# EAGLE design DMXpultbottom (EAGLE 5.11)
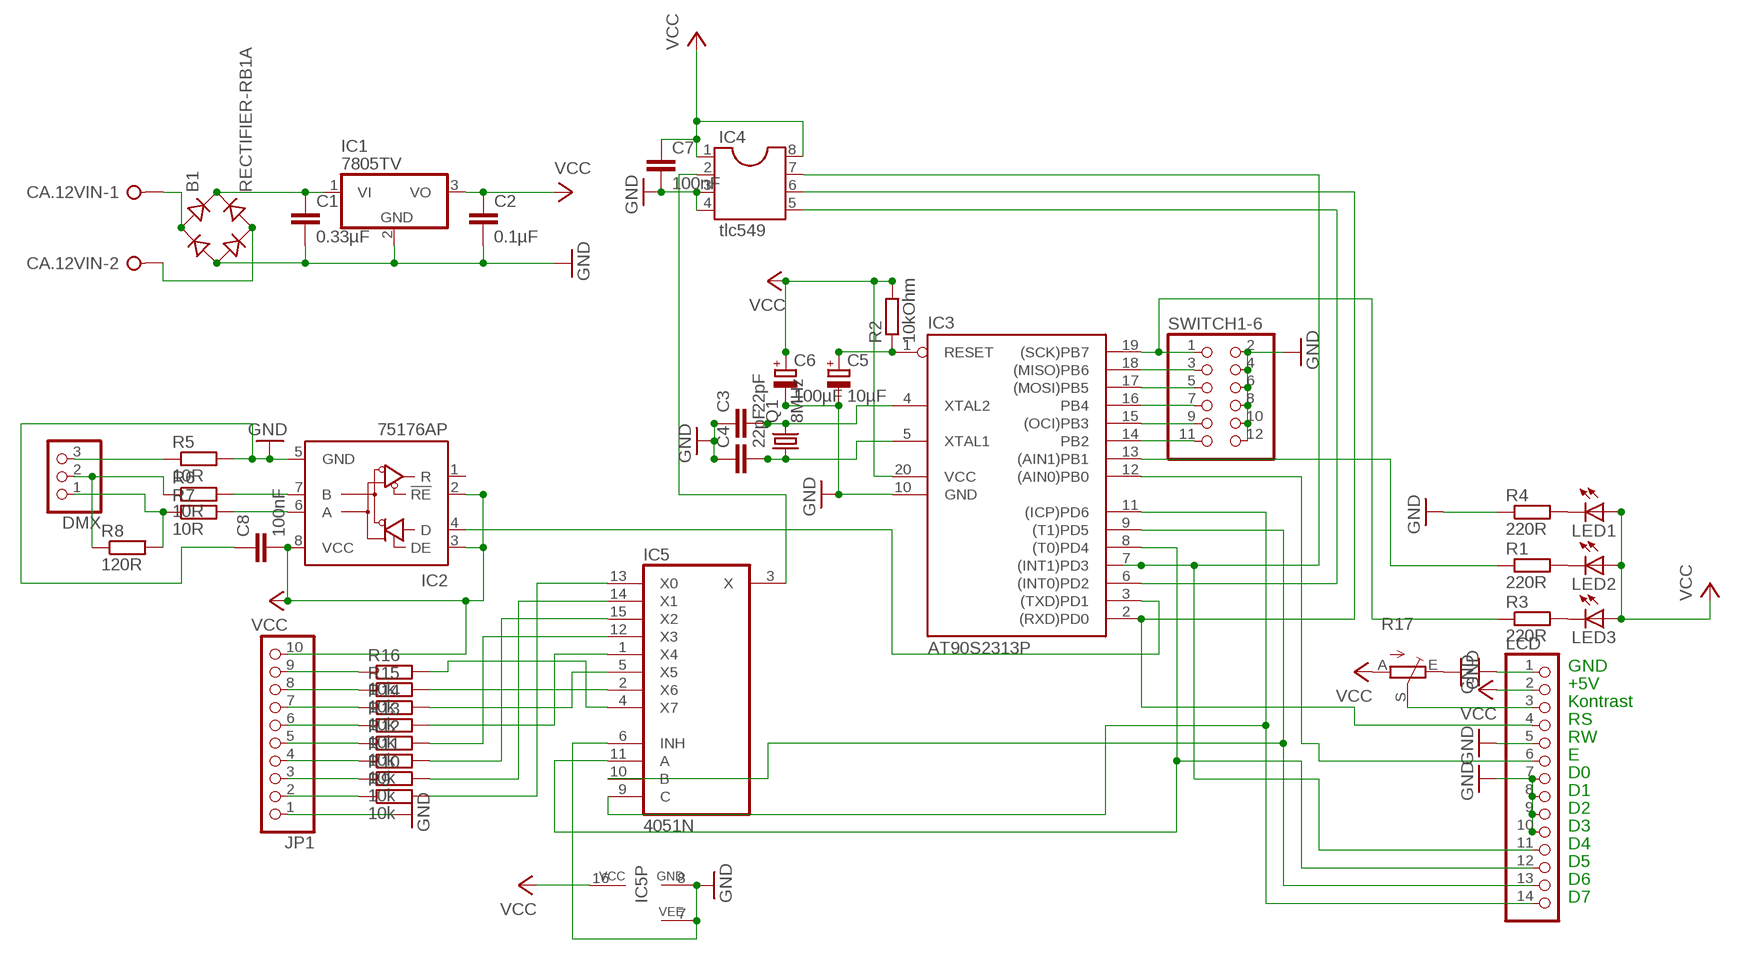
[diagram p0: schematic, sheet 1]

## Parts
B1  RECTIFIER-RB1A  [RB1A]
C1  0.33µF  C-EU025-025X050  [C025-025X050]
C2  0.1µF  C-EU025-025X050  [C025-025X050]
C3  22pF  C-EU025-024X044  [C025-024X044]
C4  22pF  C-EU025-024X044  [C025-024X044]
C5  10µF  CPOL-EUE2,5-6E  [E2,5-6E]
C6  100µF  CPOL-EUE2,5-6E  [E2,5-6E]
C7  100nF  C-EU075-042X103  [C075-042X103]
C8  100nF  C-EU075-032X103  [C075-032X103]
CA.12VIN  W237-02P  [W237-132]
DMX  PINHD-1X3  [1X03]
IC1  7805TV  [TO220V]
IC2  75176AP  [DIL08]
IC3  AT90S2313P  [DIL20]
IC4  tlc549  DIL8  [DIL08]
IC5  4051N  [DIL16]
JP1  PINHD-1X10  [1X10]
LCD  PINHD-1X14  [1X14]
LED1  LED3MM  [LED3MM]
LED2  LED3MM  [LED3MM]
LED3  LED3MM  [LED3MM]
Q1  8MHz  CRYSTALHC49U70  [HC49U70]
R1  220R  R-EU_0207/2V  [0207/2V]
R2  10kOhm  R-EU_0207/2V  [0207/2V]
R3  220R  R-EU_0207/2V  [0207/2V]
R4  220R  R-EU_0207/2V  [0207/2V]
R5  10R  R-EU_0207/2V  [0207/2V]
R6  10R  R-EU_0207/2V  [0207/2V]
R7  10R  R-EU_0207/2V  [0207/2V]
R8  120R  R-EU_0207/2V  [0207/2V]
R9  10k  R-EU_0207/2V  [0207/2V]
R10  10k  R-EU_0207/2V  [0207/2V]
R11  10k  R-EU_0207/2V  [0207/2V]
R12  10k  R-EU_0207/2V  [0207/2V]
R13  10k  R-EU_0207/2V  [0207/2V]
R14  10k  R-EU_0207/2V  [0207/2V]
R15  10k  R-EU_0207/2V  [0207/2V]
R16  10k  R-EU_0207/2V  [0207/2V]
R17  TRIM_EU-B64Y  [B64Y]
SWITCH1-6  PINHD-2X6  [2X06]

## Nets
GND: B1.- C1.2 C2.2 C3.1 C4.1 C5.- C6.- C7.2 C8.1 IC1.2(GND) IC2.5(GND) IC3.10(GND) IC4.3 IC4.4 IC5.6(INH) IC5.7(VEE) IC5.8(GND) JP1.1 LCD.1 LCD.5 LCD.7 LCD.8 LCD.9 LCD.10 R4.1 R5.2 R17.E SWITCH1-6.2 SWITCH1-6.4 SWITCH1-6.6 SWITCH1-6.8 SWITCH1-6.10 SWITCH1-6.12
N$1: IC3.8((T0)PD4) IC5.11(A) LCD.12
N$2: B1.+ C1.1 IC1.1(VI)
N$4: IC3.9((T1)PD5) IC5.10(B) LCD.13
N$5: C5.+ IC3.1(RESET) R2.1
N$6: IC3.2((RXD)PD0) IC4.6 LCD.4
N$7: IC2.4(D) IC3.3((TXD)PD1)
N$8: IC3.6((INT0)PD2) IC4.5
N$9: IC3.7((INT1)PD3) IC4.7 LCD.11
N$10: IC3.11((ICP)PD6) IC5.9(C) LCD.14
N$11: LED2.K(C) R1.2
N$12: IC3.12((AIN0)PB0) LCD.6
N$13: IC3.18((MISO)PB6) SWITCH1-6.3
N$14: IC3.17((MOSI)PB5) SWITCH1-6.5
N$15: IC3.16(PB4) SWITCH1-6.7
N$16: IC3.15((OCI)PB3) SWITCH1-6.9
N$17: IC3.19((SCK)PB7) R3.1 SWITCH1-6.1
N$18: C4.2 IC3.5(XTAL1) Q1.1
N$19: IC3.13((AIN1)PB1) R1.1
N$20: LED3.K(C) R3.2
N$21: LED1.K(C) R4.2
N$22: JP1.9 R16.1
N$23: JP1.8 R15.1
N$24: JP1.7 R14.1
N$25: IC4.2 IC5.3(X)
N$26: JP1.6 R13.1
N$27: IC2.7(B) R6.2
N$28: IC2.6(A) R7.2
N$29: DMX.3 R5.1
N$30: DMX.2 R6.1 R8.1
N$31: DMX.1 R7.1 R8.2
N$32: JP1.5 R12.1
N$33: JP1.3 R10.1
N$34: IC5.13(X0) R9.2
N$35: IC5.14(X1) R10.2
N$36: IC5.15(X2) R11.2
N$37: IC5.12(X3) R12.2
N$38: IC5.1(X4) R13.2
N$39: IC5.5(X5) R14.2
N$40: IC5.2(X6) R15.2
N$41: IC5.4(X7) R16.2
N$42: JP1.2 R9.1
N$43: JP1.4 R11.1
N$44: C3.2 IC3.4(XTAL2) Q1.2
N$45: B1.AC2 CA.12VIN.2
N$46: B1.AC1 CA.12VIN.1
N$47: LCD.3 R17.S
N$48: IC3.14(PB2) SWITCH1-6.11
VCC: C2.1 C6.+ C7.1 C8.2 IC1.3(VO) IC2.2(!RE) IC2.3(DE) IC2.8(VCC) IC3.20(VCC) IC4.1 IC4.8 IC5.16(VCC) JP1.10 LCD.2 LED1.A LED2.A LED3.A R2.2 R17.A
Unconnected: IC2.1(R)

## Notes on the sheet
- GND
- +5V
- Kontrast
- RS
- RW
- E
- D0
- D1
- D2
- D3
- D4
- D5
- D6
- D7

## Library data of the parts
B1 = rectifier:RECTIFIER-: Rectifier
C1-C4 C7 C8 = resistor:C-EU: CAPACITOR, European symbol
C5 C6 = resistor:CPOL-EU: POLARIZED CAPACITOR, European symbol
CA.12VIN = con-wago-508:W237-02P: WAGO SREW CLAMP; OC_FARNELL: unknown; OC_NEWARK: unknown
DMX = pinhead:PINHD-1X3: PIN HEADER
IC1 = linear:78*: Positive VOLTAGE REGULATOR Source: http://cache.national.com/ds/LM/LM78L05.pdf http://www.fairchildsemi.com/ds/LM/LM7805.pdf
IC2 = 751xx:75176A: DIFFERENTIAL BUS TRANSCEIVER Source: http://focus.ti.com/lit/ds/symlink/sn75176a.pdf
IC3 = atmel:AT90S2313: MICROCONTROLLER 2 Kbytes FLASH 128 bytes SRAM 128 bytes EEPROM UART; OC_FARNELL: unknown; OC_NEWARK: unknown
IC4 = ic-package:DIL8: Dual In Line / Socket
IC5 = 40xx:4051: 8-channel ANALOG MULTIPLEXER
JP1 = pinhead:PINHD-1X10: PIN HEADER
LCD = pinhead:PINHD-1X14: PIN HEADER
LED1-LED3 = led:LED: LED
Q1 = crystal:CRYSTAL: CRYSTAL; OC_FARNELL: unknown; OC_NEWARK: unknown
R1-R16 = resistor:R-EU_: RESISTOR, European symbol
R17 = pot:TRIM_EU-: POTENTIOMETER
SWITCH1-6 = pinhead:PINHD-2X6: PIN HEADER

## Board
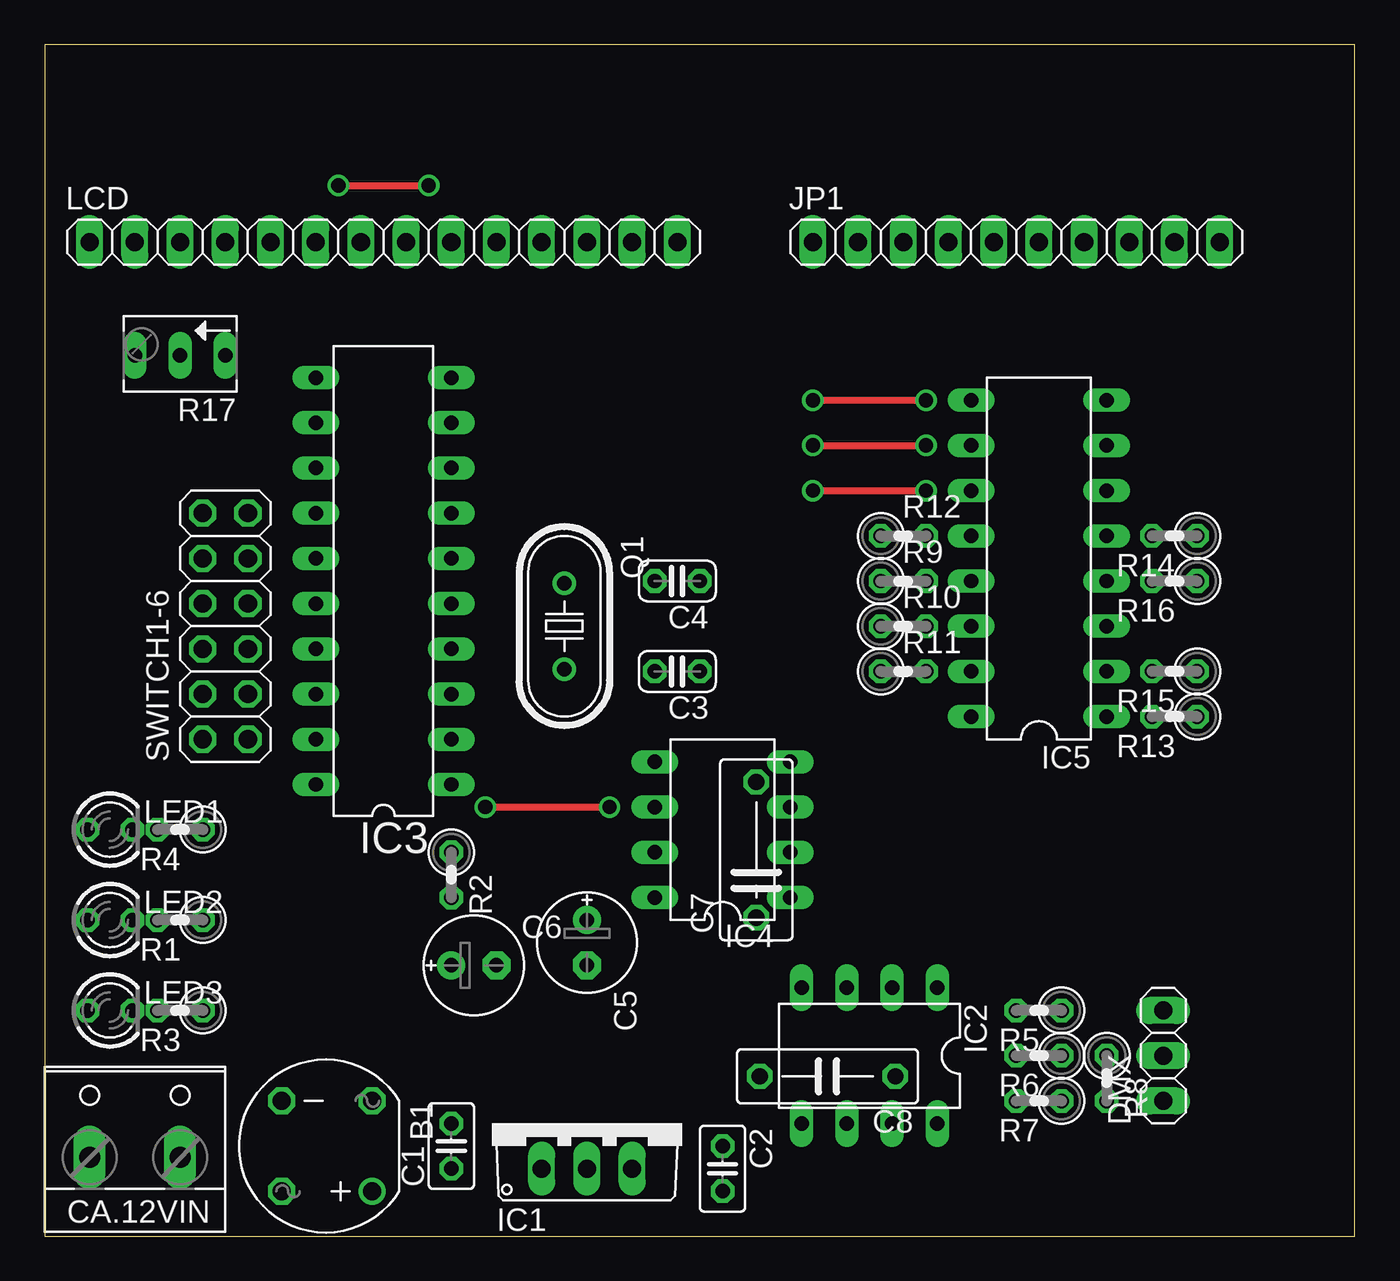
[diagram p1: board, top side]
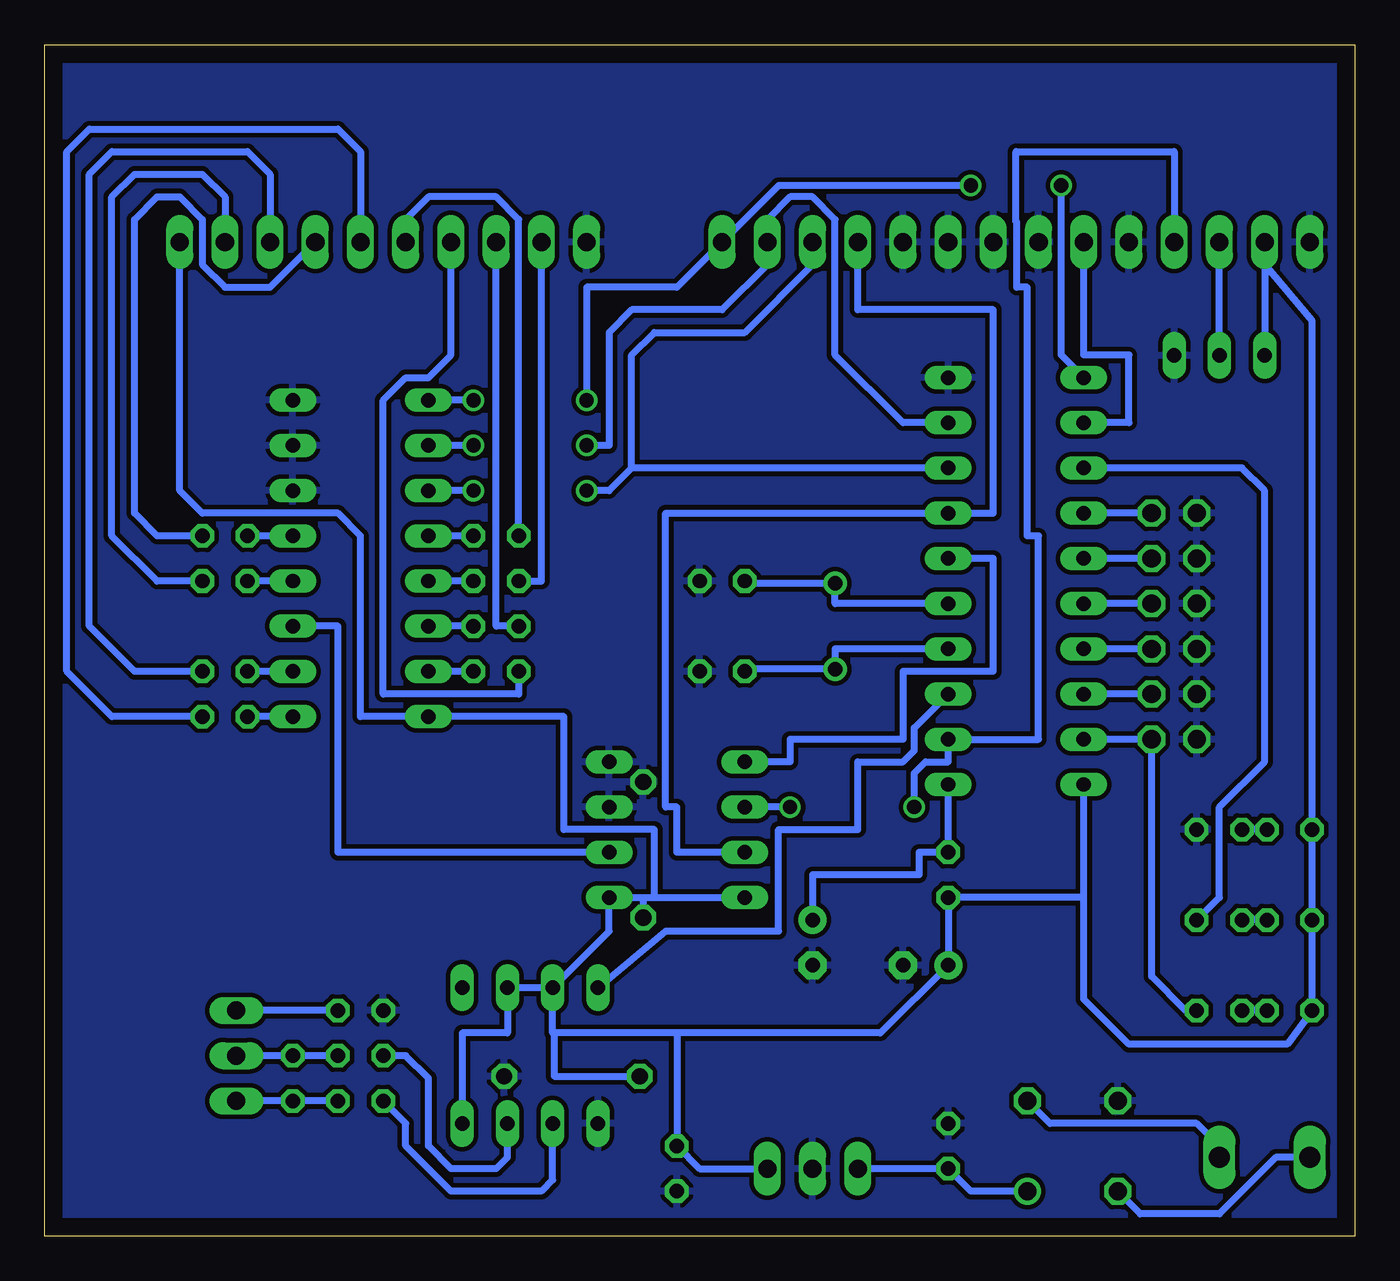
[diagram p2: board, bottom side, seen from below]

Size 73.64 x 66.98 mm. Coordinates in mm from the lower left corner, seen from the top.
Outline: 0,0 73.64,0 73.64,66.98 0,66.98 0,0
Copper layers (1*16): Top 0.035mm / dielectric 1.5mm / Bottom 0.035mm
Design rules "default": minimum track width 10mil, minimum drill 24mil, track to track 8mil, track to pad 8mil, pad to pad 8mil, via to via 8mil, smd to smd 8mil, copper to edge 40mil, drill to drill 8mil, minimum pad ring 10mil, minimum via ring 8mil, stop-mask expansion 4mil, vias tented up to drill 0mil, thermal gap 10mil

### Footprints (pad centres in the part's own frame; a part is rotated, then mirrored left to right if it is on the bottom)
RB1A = drill 1.016 round: + -2.54,2.54 | drill 1.016 octagon: - 2.54,-2.54; AC1 2.54,2.54; AC2 -2.54,-2.54
C025-025X050 = drill 0.813 octagon: 1 -1.27,0; 2 1.27,0
C025-024X044 = drill 0.813 octagon: 1 -1.27,0; 2 1.27,0
E2,5-6E = drill 0.813 pad 1.575 round: + -1.27,0 | drill 0.813 pad 1.575 octagon: - 1.27,0
C075-042X103 = drill 0.914 octagon: 1 -3.81,0; 2 3.81,0
C075-032X103 = drill 0.914 octagon: 1 -3.81,0; 2 3.81,0
W237-132 = drill 1.194 long: 1 -2.54,-0.635; 2 2.54,-0.635
1X03 = drill 1.016 long: 1 -2.54,0; 2 0,0; 3 2.54,0
TO220V = drill 1.016 long: 1 -2.54,-2.54; 2 0,-2.54; 3 2.54,-2.54
DIL08 = drill 0.813 long: 1 -3.81,-3.81; 2 -1.27,-3.81; 3 1.27,-3.81; 4 3.81,-3.81; 5 3.81,3.81; 6 1.27,3.81; 7 -1.27,3.81; 8 -3.81,3.81
DIL20 = drill 0.813 long: 1 -11.43,-3.81; 2 -8.89,-3.81; 3 -6.35,-3.81; 4 -3.81,-3.81; 5 -1.27,-3.81; 6 1.27,-3.81; 7 3.81,-3.81; 8 6.35,-3.81; 9 8.89,-3.81; 10 11.43,-3.81; 11 11.43,3.81; 12 8.89,3.81; 13 6.35,3.81; 14 3.81,3.81; 15 1.27,3.81; 16 -1.27,3.81; 17 -3.81,3.81; 18 -6.35,3.81; 19 -8.89,3.81; 20 -11.43,3.81
DIL16 = drill 0.813 long: 1 -8.89,-3.81; 2 -6.35,-3.81; 3 -3.81,-3.81; 4 -1.27,-3.81; 5 1.27,-3.81; 6 3.81,-3.81; 7 6.35,-3.81; 8 8.89,-3.81; 9 8.89,3.81; 10 6.35,3.81; 11 3.81,3.81; 12 1.27,3.81; 13 -1.27,3.81; 14 -3.81,3.81; 15 -6.35,3.81; 16 -8.89,3.81
1X10 = drill 1.016 long: 1 -11.43,0; 2 -8.89,0; 3 -6.35,0; 4 -3.81,0; 5 -1.27,0; 6 1.27,0; 7 3.81,0; 8 6.35,0; 9 8.89,0; 10 11.43,0
1X14 = drill 1.016 long: 1 -16.51,0; 2 -13.97,0; 3 -11.43,0; 4 -8.89,0; 5 -6.35,0; 6 -3.81,0; 7 -1.27,0; 8 1.27,0; 9 3.81,0; 10 6.35,0; 11 8.89,0; 12 11.43,0; 13 13.97,0; 14 16.51,0
LED3MM = drill 0.813 octagon: A -1.27,0; K 1.27,0
HC49U70 = drill 0.813 round: 1 -2.413,0; 2 2.413,0
0207/2V = drill 0.813 octagon: 1 -1.27,0; 2 1.27,0
B64Y = drill 0.813 long: A 2.54,0; E -2.54,0; S 0,0
2X06 = drill 1.016 octagon: 1 -6.35,-1.27; 2 -6.35,1.27; 3 -3.81,-1.27; 4 -3.81,1.27; 5 -1.27,-1.27; 6 -1.27,1.27; 7 1.27,-1.27; 8 1.27,1.27; 9 3.81,-1.27; 10 3.81,1.27; 11 6.35,-1.27; 12 6.35,1.27

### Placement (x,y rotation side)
B1  15.88,5.08 180 top
C1  22.86,5.08 90 top
C2  38.1,3.81 270 top
C3  35.56,31.75 180 top
C4  35.56,36.83 180 top
C5  30.48,16.51 270 top
C6  24.13,15.24 0 top
C7  40,21.73 90 top
C8  44,9 180 top
CA.12VIN  5.08,5.08 0 top
DMX  62.87,10.16 90 top
IC1  30.48,6.35 0 top
IC2  46.35,10.16 180 top
IC3  19.05,36.83 90 top
IC4  38.1,22.86 90 top
IC5  55.88,38.1 90 top
JP1  54.61,55.88 0 top
LCD  19.05,55.88 0 top
LED1  3.67,22.86 0 top
LED2  3.67,17.78 0 top
LED3  3.67,12.7 0 top
Q1  29.21,34.29 270 top
R1  7.62,17.78 180 top
R2  22.86,20.32 270 top
R3  7.62,12.7 180 top
R4  7.62,22.86 180 top
R5  55.88,12.7 180 top
R6  55.88,10.16 180 top
R7  55.88,7.62 180 top
R8  59.69,8.89 270 top
R9  48.26,36.83 0 top
R10  48.26,34.29 0 top
R11  48.26,31.75 0 top
R12  48.26,39.37 0 top
R13  63.5,29.21 180 top
R14  63.5,39.37 180 top
R15  63.5,31.75 180 top
R16  63.5,36.83 180 top
R17  7.62,49.5 180 top
SWITCH1-6  10.16,34.29 90 top

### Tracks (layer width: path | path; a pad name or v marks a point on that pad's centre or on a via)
GND
  pour Bottom (isolate 0.254): -1.27,68.58 74.93,68.58 74.93,-1.27 -1.27,-1.27
N$1  (via drill 0.8)
  Top 0.406: v43.18,41.91 v49.53,41.91
  Bottom 0.406: v49.53,41.91 IC5.11 | v43.18,41.91 41.91,41.91 40.64,43.18 | 40.64,43.18 40.64,49.53 39.37,50.8 34.29,50.8 30.48,54.61 LCD.12 | IC3.8 40.64,43.18
N$2
  Bottom 0.406: B1.+ 21.59,2.54 C1.1 IC1.1
N$4  (via drill 0.8)
  Top 0.406: v43.18,44.45 v49.53,44.45
  Bottom 0.406: v49.53,44.45 IC5.10 | v43.18,44.45 41.91,44.45 41.91,50.8 40.64,52.07 35.56,52.07 33.02,54.61 LCD.13 33.02,57.15 31.75,58.42 30.48,58.42 29.21,57.15 29.21,49.53 25.4,45.72 IC3.9
N$5
  Bottom 0.406: IC3.1 R2.1 24.5,21.59 24.5,20.32 30.48,20.32 C5.+
N$6  (via drill 0.8)
  Top 0.406: v24.77,24.13 v31.75,24.13
  Bottom 0.406: LCD.4 10.16,60.96 19.05,60.96 19.05,57 19,57 19,53.34 18.41,53.34 18.41,39.37 17.78,39.37 17.78,27.94 IC3.2 22.86,26.67 24.13,26.67 24.77,26.04 v24.77,24.13 | v31.75,24.13 IC4.6
N$7
  Bottom 0.406: IC2.4 38.73,17.14 32.38,17.14 32.38,22.86 27.94,22.86 27.94,26.67 25.4,26.67 24.77,27.3 24.77,28.57 IC3.3
N$8
  Bottom 0.406: IC4.5 31.75,26.67 31.75,27.94 25.4,27.94 25.4,31.75 20.32,31.75 20.32,38.1 IC3.6
N$9
  Bottom 0.406: LCD.11 27.94,52.07 20.32,52.07 20.32,40.64 IC3.7 38.73,40.64 38.73,24.13 38.1,24.13 38.1,21.59 IC4.7
N$10  (via drill 0.8)
  Top 0.406: v43.18,46.99 v49.53,46.99 | v16.51,59.05 v21.59,59.05
  Bottom 0.406: v49.53,46.99 IC5.9 | v43.18,46.99 43.18,53.34 38.1,53.34 LCD.14 32.38,59.05 v21.59,59.05 | IC3.11 16.51,49.53 v16.51,59.05
N$11
  Bottom 0.406: LED2.K R1.2
N$12
  Bottom 0.406: LCD.6 15.24,49.53 12.7,49.53 12.7,45.72 IC3.12
N$13
  Bottom 0.406: SWITCH1-6.3 IC3.18
N$14
  Bottom 0.406: SWITCH1-6.5 IC3.17
N$15
  Bottom 0.406: SWITCH1-6.7 IC3.16
N$16
  Bottom 0.406: SWITCH1-6.9 IC3.15
N$17
  Bottom 0.406: IC3.19 SWITCH1-6.1 11.43,14.61 9.53,12.7 R3.1
N$18
  Bottom 0.406: IC3.5 29.21,35.56 Q1.1 34.29,36.7 C4.2
N$19
  Bottom 0.406: IC3.13 6.35,43.18 5.08,41.91 5.08,26.67 7.62,24.13 7.62,19.05 R1.1
N$20
  Bottom 0.406: LED3.K R3.2
N$21
  Bottom 0.406: LED1.K R4.2
N$22
  Bottom 0.406: JP1.9 63.5,58.42 64.77,59.69 68.58,59.69 69.85,58.42 69.85,39.37 67.31,36.83 R16.1
N$23
  Bottom 0.406: R15.1 68.58,31.75 71.12,34.29 71.12,59.69 69.85,60.96 62.23,60.96 60.96,59.69 JP1.8
N$24
  Bottom 0.406: R14.1 67.31,39.37 68.58,40.64 68.58,57.15 67.31,58.42 66.04,58.42 64.77,57.15 64.77,54.61 63.5,53.34 60.96,53.34 JP1.7
N$25
  Bottom 0.406: IC4.2 57.15,21.59 57.15,34.29 IC5.3
N$26
  Bottom 0.406: JP1.6 55.88,60.96 57.15,62.23 71.12,62.23 72.39,60.96 72.39,31.75 69.85,29.21 R13.1
N$27
  Bottom 0.406: R6.2 53.34,10.16 52.07,8.89 52.07,5.08 50.8,3.81 48.26,3.81 47.62,4.45 IC2.7
N$28
  Bottom 0.406: IC2.6 45.09,3.17 45.72,2.54 50.8,2.54 53.34,5.08 53.34,6.35 R7.2
N$29
  Bottom 0.406: R5.1 DMX.3
N$30
  Bottom 0.406: DMX.2 R8.1 R6.1
N$31
  Bottom 0.406: DMX.1 R8.2 R7.1
N$32
  Bottom 0.406: R12.1 46.99,57.15 48.26,58.42 52.07,58.42 53.34,57.15 JP1.5
N$33
  Bottom 0.406: R10.1 48.26,34.29 JP1.3
N$34
  Bottom 0.406: R9.2 IC5.13
N$35
  Bottom 0.406: R10.2 IC5.14
N$36
  Bottom 0.406: R11.2 IC5.15
N$37
  Bottom 0.406: R12.2 IC5.12
N$38
  Bottom 0.406: IC5.1 R13.2
N$39
  Bottom 0.406: IC5.5 R14.2
N$40
  Bottom 0.406: IC5.2 R15.2
N$41
  Bottom 0.406: IC5.4 R16.2
N$42
  Bottom 0.406: R9.1 45.72,36.83 JP1.2
N$43
  Bottom 0.406: R11.1 46.99,30.48 54.61,30.48 54.61,46.99 53.34,48.26 52.07,48.26 50.8,49.53 JP1.4
N$44
  Bottom 0.406: IC3.4 29.21,33.02 Q1.2 34.29,31.88 C3.2
N$45
  Bottom 0.406: CA.12VIN.2 7.62,5.08 8.89,6.35 17.14,6.35 B1.AC2
N$46
  Bottom 0.406: CA.12VIN.1 4.45,4.45 7.62,1.27 12.06,1.27 B1.AC1
N$47
  Bottom 0.406: R17.S LCD.3
N$48
  Bottom 0.406: SWITCH1-6.11 IC3.14
VCC
  Bottom 0.406: R17.A LCD.2 5.08,54.61 2.4,51.44 LED1.A LED2.A LED3.A 3.81,10.79 12.7,10.79 15.24,13.34 15.24,19.05 | 15.24,19.05 R2.2 C6.+ 26.67,11.43 38.1,11.43 | 15.24,19.05 IC3.20 | 38.1,11.43 45,11.43 | 45,11.43 45.09,11.43 IC2.3 | IC2.3 IC2.2 | IC2.2 46.99,13.97 | 40,19.05 IC4.1 41.91,17.14 IC2.3 | 40,19.05 39.37,19.05 | 39.37,19.05 IC4.8 | IC2.8 50.16,11.43 47.62,11.43 IC2.2 | 39.37,19.05 39.37,22.86 44.45,22.86 44.45,29.21 IC5.16 55.88,29.21 55.88,39.37 57.15,40.64 64.77,40.64 66.04,41.91 JP1.10 | IC1.3 36.83,3.81 C2.1 38.1,11.43 | 40,19.05 C7.1 | C8.2 45,9 45,11.43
